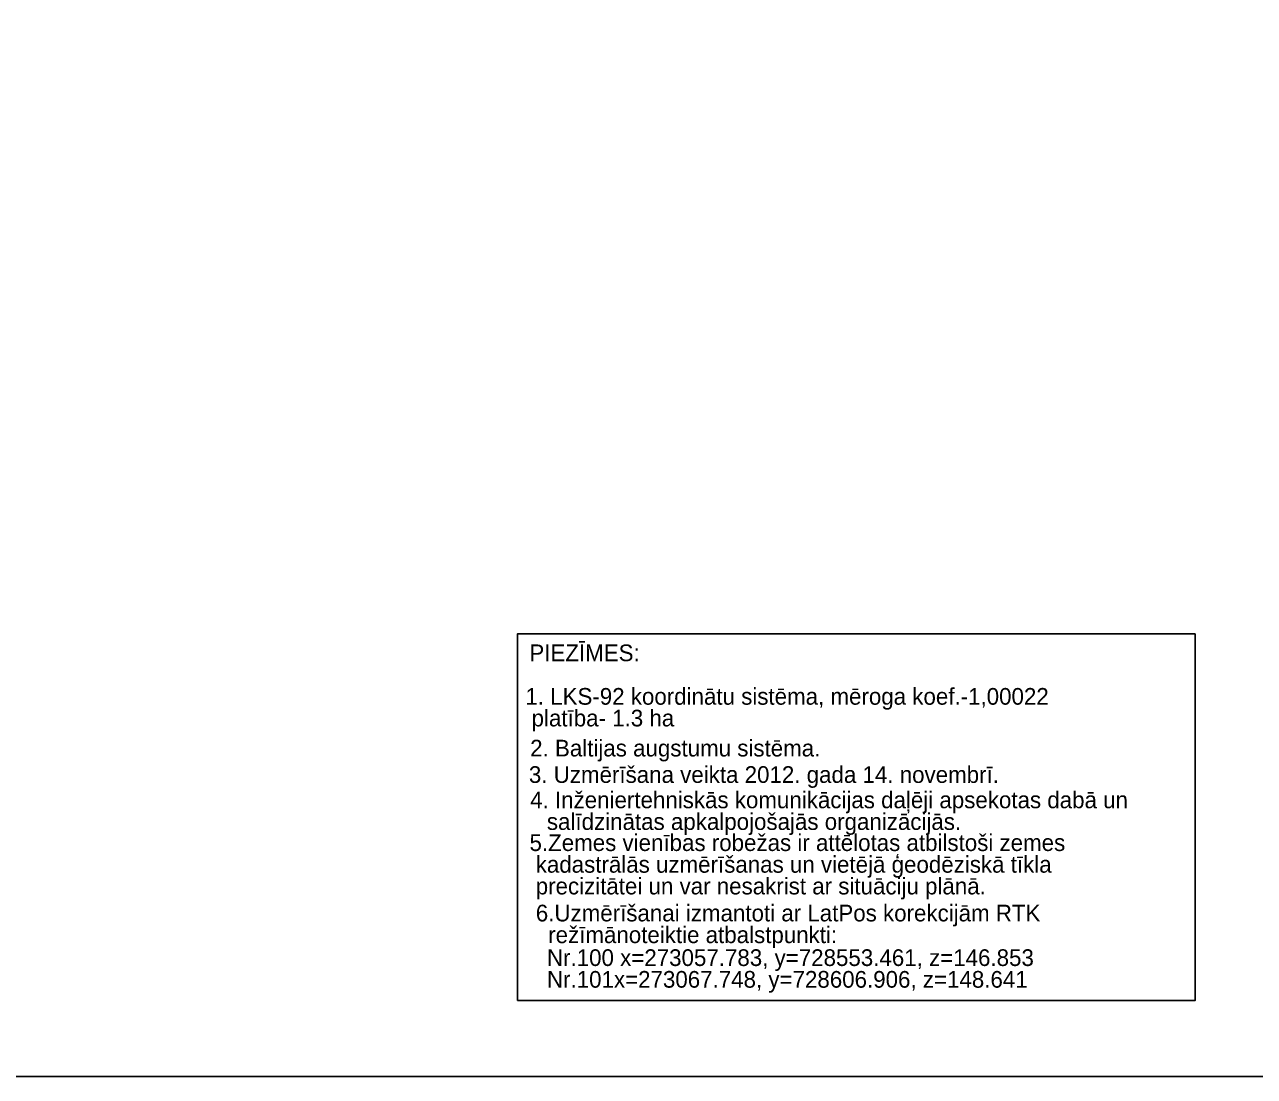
# Model space of a CAD drawing. Extents: x 728492 to 729038, y 272968 to 273171.
# Drawn here: x 728626.4 to 728700.1, y 272968.3 to 273031.3 of the extents above; entities that cross this region are included whole.
import ezdxf

# ---------------------------------------------------------------- set-up
doc = ezdxf.new("R2010")
doc.units = 0
doc.layers.add('RAMI_PLAN_####_TKST_#', color=7, linetype='Continuous')

msp = doc.modelspace()

# ---------------------------------------------------------------- linework, layer by layer
at = {"layer": 'RAMI_PLAN_####_TKST_#'}
for points in [[(728492.227, 273152.288), (728492.227, 272968.263), (728765.305, 272968.263), (728765.305, 273152.288)], [(728655.959, 272972.804), (728696.581, 272972.804), (728696.581, 272994.764), (728655.959, 272994.764)]]:
    msp.add_lwpolyline(points, close=True, dxfattribs=at)

# ---------------------------------------------------------------- texts
for s, p in [('PIEZĪMES:', (728656.678, 272993.134)), ('1. LKS-92 koordinātu sistēma, mēroga koef.-1,00022', (728656.438, 272990.526)), (' platība- 1.3 ha', (728656.438, 272989.226)), ('2. Baltijas augstumu sistēma.', (728656.725, 272987.426)), ('3. Uzmērīšana veikta 2012. gada 14. novembrī.', (728656.649, 272985.843)), ('4. Inženiertehniskās komunikācijas daļēji apsekotas dabā un ', (728656.725, 272984.325)), ('salīdzinātas apkalpojošajās organizācijās.', (728657.728, 272983.026)), ('5.Zemes vienības robežas ir attēlotas atbilstoši zemes', (728656.686, 272981.763)), (' kadastrālās uzmērīšanas un vietējā ģeodēziskā tīkla ', (728656.686, 272980.463)), (' precizitātei un var nesakrist ar situāciju plānā.', (728656.686, 272979.163)), ('6.Uzmērīšanai izmantoti ar LatPos korekcijām RTK ', (728657.063, 272977.547)), ('  režīmānoteiktie atbalstpunkti:', (728657.063, 272976.247)), ('Nr.100 x=273057.783, y=728553.461, z=146.853', (728657.732, 272974.876)), ('Nr.101x=273067.748, y=728606.906, z=148.641', (728657.732, 272973.576))]:
    msp.add_text(s, height=1, rotation=359.99995, dxfattribs=at).set_placement(p)

doc.saveas('drawing.dxf')
